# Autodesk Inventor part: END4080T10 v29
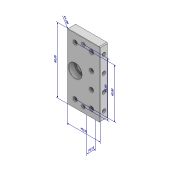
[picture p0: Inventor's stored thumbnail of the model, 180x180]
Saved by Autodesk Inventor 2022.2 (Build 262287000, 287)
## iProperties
Created: 2024-09
Part Number: END4080T10 v29
Material: 钢
Document SubType Name: Modeling
Designer: 18907419
Density: 7.85 g/cm^3
Appearance: Default
Author: 18907419
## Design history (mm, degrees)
node "Annotazioni"
  node "Quota lineare 2" dims "d5" = 80 (derived)
  node "Quota radiale 1" dims "d7" = 1 (derived)
  node "Quota lineare 3" dims "d8" = 60 (derived)
  node "Quota lineare 4" dims "d9" = 66 (derived)
  node "Quota lineare 5" dims "d12" = 40 (derived)
  node "Quota lineare 6" dims "d15" = 10 (derived)
feature "Solido1"
node "Solido2"
other parameters: "d10" = 1.87171 (derived), "d11" = 9.24914 (derived), "d13" = 6.11896 (derived), "d14" = 1.71037 (derived), "d3" = 8.60263 (derived), "d4" = 1.0104 (derived), "d6" = 60.6 (derived)
